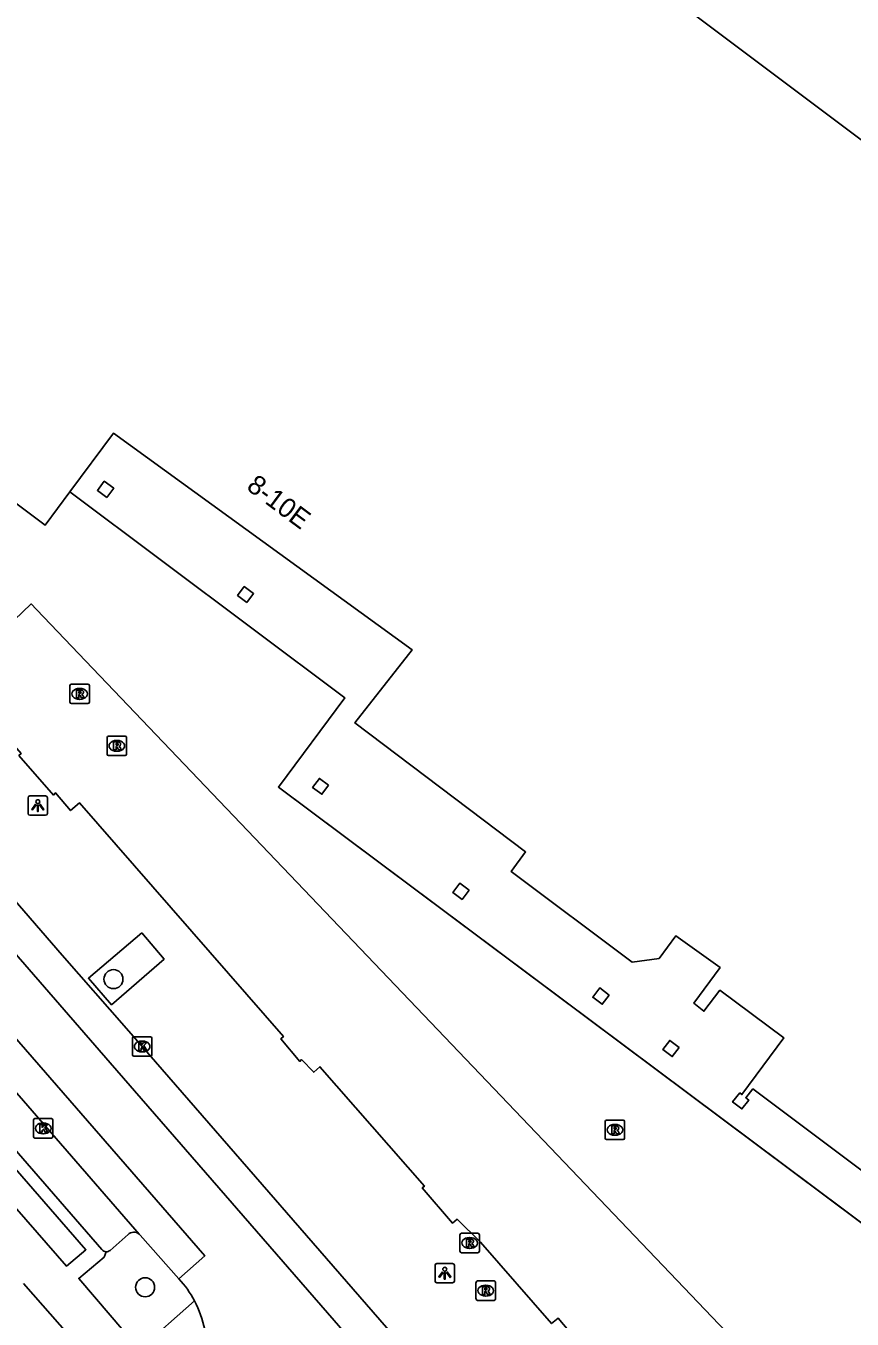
# Model space of a CAD drawing. Extents: x 159718 to 160783, y 383290 to 384030.
# Drawn here: x 160515.5 to 160558, y 383529.7 to 383596.2 of the extents above; entities that cross this region are included whole.
import ezdxf

# ---------------------------------------------------------------- set-up
doc = ezdxf.new("R2010")
doc.units = 0
for name, color, linetype in [('IMGEO_Boom', 7, 'Continuous'), ('IMGEO_Kolk', 7, 'Continuous'), ('IMGEO_Lichtpunt', 7, 'Continuous'), ('IMGEO_Pand', 7, 'Continuous'), ('IMGEO_Pand_nummerreeks', 7, 'Continuous'), ('IMGEO_Pand_overbouw', 7, 'Continuous'), ('IMGEO_Parkeervlak_open', 7, 'Continuous'), ('IMGEO_Rijbaan_lokaal_gesloten', 7, 'Continuous'), ('IMGEO_Rijbaan_lokaal_open', 7, 'Continuous'), ('IMGEO_Rioolput', 7, 'Continuous'), ('IMGEO_Voetpad_open', 7, 'Continuous')]:
    doc.layers.add(name, color=color, linetype=linetype)

msp = doc.modelspace()

# ---------------------------------------------------------------- linework, layer by layer
at = {"layer": 'IMGEO_Boom'}
for centre in [(160520.043, 383547.221), (160521.671, 383531.372)]:
    msp.add_circle(centre, 0.489, dxfattribs=at)
at = {"layer": 'IMGEO_Kolk'}
for p, q in [((160521.019, 383543.333), (160521.019, 383544.185)), ((160521.094, 383544.259), (160521.946, 383544.259)), ((160522.02, 383544.185), (160522.02, 383543.333)), ((160521.53, 383543.479), (160521.505, 383543.479)), ((160521.507, 383544.039), (160521.532, 383544.039)), ((160521.946, 383543.259), (160521.094, 383543.259)), ((160515.929, 383539.121), (160515.929, 383539.973)), ((160516.004, 383540.047), (160516.856, 383540.047)), ((160516.417, 383539.827), (160516.442, 383539.827)), ((160516.93, 383539.973), (160516.93, 383539.121)), ((160516.856, 383539.047), (160516.004, 383539.047)), ((160516.44, 383539.267), (160516.415, 383539.267))]:
    msp.add_line(p, q, dxfattribs=at)
for points in [[(160521.019, 383543.333), (160521.019, 383544.185)], [(160521.094, 383544.259), (160521.946, 383544.259)], [(160522.02, 383544.185), (160522.02, 383543.333)], [(160521.34, 383543.959), (160521.463, 383543.959), (160521.463, 383543.808), (160521.593, 383543.959), (160521.757, 383543.959), (160521.611, 383543.808), (160521.764, 383543.559), (160521.612, 383543.559), (160521.527, 383543.723), (160521.463, 383543.656), (160521.463, 383543.559), (160521.34, 383543.559), (160521.34, 383543.959)], [(160521.946, 383543.259), (160521.094, 383543.259)], [(160515.929, 383539.121), (160515.929, 383539.973)], [(160516.004, 383540.047), (160516.856, 383540.047)], [(160516.25, 383539.747), (160516.373, 383539.747), (160516.373, 383539.596), (160516.503, 383539.747), (160516.667, 383539.747), (160516.521, 383539.596), (160516.674, 383539.347), (160516.522, 383539.347), (160516.437, 383539.511), (160516.373, 383539.444), (160516.373, 383539.347), (160516.25, 383539.347), (160516.25, 383539.747)], [(160516.93, 383539.973), (160516.93, 383539.121)], [(160516.856, 383539.047), (160516.004, 383539.047)]]:
    msp.add_lwpolyline(points, dxfattribs=at)
for centre, start, end in [((160521.096, 383544.183), 91.55205, 178.44795), ((160521.096, 383544.183), 91.55205, 178.44795), ((160521.944, 383544.183), 1.55205, 88.44795), ((160521.944, 383544.183), 1.55205, 88.44795), ((160521.096, 383543.335), 181.55205, 268.44795), ((160521.096, 383543.335), 181.55205, 268.44795), ((160521.944, 383543.335), 271.55205, 358.44795), ((160521.944, 383543.335), 271.55205, 358.44795), ((160516.006, 383539.971), 91.55205, 178.44795), ((160516.006, 383539.971), 91.55205, 178.44795), ((160516.854, 383539.971), 1.55205, 88.44795), ((160516.854, 383539.971), 1.55205, 88.44795), ((160516.006, 383539.123), 181.55205, 268.44795), ((160516.006, 383539.123), 181.55205, 268.44795), ((160516.854, 383539.123), 271.55205, 358.44795), ((160516.854, 383539.123), 271.55205, 358.44795)]:
    msp.add_arc(centre, 0.0765, start, end, dxfattribs=at)
for centre, major_axis, ratio, start_param, end_param in [((160521.506, 383543.759), (-0.387, 0.002), 0.722429, 4.712389, 7.853982), ((160521.531, 383543.759), (-0.39, 0.002), 0.717154, 1.570796, 4.712389), ((160516.416, 383539.547), (-0.387, 0.002), 0.722429, 4.712389, 7.853982), ((160516.441, 383539.547), (-0.39, 0.002), 0.717154, 1.570796, 4.712389)]:
    msp.add_ellipse(centre, major_axis=major_axis, ratio=ratio, start_param=start_param, end_param=end_param, dxfattribs=at)
at = {"layer": 'IMGEO_Lichtpunt'}
for p, q in [((160515.652, 383556.55), (160515.652, 383555.743)), ((160515.652, 383556.55), (160515.652, 383555.743)), ((160516.554, 383556.645), (160515.746, 383556.645)), ((160516.554, 383556.645), (160515.746, 383556.645)), ((160516.648, 383555.743), (160516.648, 383556.55)), ((160516.648, 383555.743), (160516.648, 383556.55)), ((160515.746, 383555.649), (160516.554, 383555.649)), ((160515.746, 383555.649), (160516.554, 383555.649)), ((160536.583, 383532.503), (160536.583, 383531.696)), ((160536.583, 383532.503), (160536.583, 383531.696)), ((160537.485, 383532.598), (160536.677, 383532.598)), ((160537.485, 383532.598), (160536.677, 383532.598)), ((160537.579, 383531.696), (160537.579, 383532.503)), ((160537.579, 383531.696), (160537.579, 383532.503)), ((160536.677, 383531.602), (160537.485, 383531.602)), ((160536.677, 383531.602), (160537.485, 383531.602))]:
    msp.add_line(p, q, dxfattribs=at)
for points in [[(160516.026, 383556.214), (160516.065, 383556.186), (160515.877, 383555.924), (160515.839, 383555.951), (160516.026, 383556.214)], [(160516.128, 383556.166), (160516.175, 383556.166), (160516.175, 383555.844), (160516.128, 383555.844), (160516.128, 383556.166)], [(160516.238, 383556.186), (160516.276, 383556.213), (160516.463, 383555.951), (160516.424, 383555.923), (160516.238, 383556.186)], [(160536.957, 383532.167), (160536.996, 383532.139), (160536.808, 383531.877), (160536.77, 383531.904), (160536.957, 383532.167)], [(160537.169, 383532.139), (160537.207, 383532.166), (160537.394, 383531.904), (160537.355, 383531.876), (160537.169, 383532.139)], [(160537.059, 383532.119), (160537.106, 383532.119), (160537.106, 383531.797), (160537.059, 383531.797), (160537.059, 383532.119)]]:
    msp.add_lwpolyline(points, dxfattribs=at)
for centre in [(160516.151, 383556.348), (160537.082, 383532.301)]:
    msp.add_circle(centre, 0.0994, dxfattribs=at)
for centre, start, end in [((160515.746, 383556.55), 90, 180), ((160515.746, 383556.55), 90, 180), ((160516.554, 383556.55), 0, 90), ((160516.554, 383556.55), 0, 90), ((160515.746, 383555.743), 180, 270), ((160515.746, 383555.743), 180, 270), ((160516.554, 383555.743), 270, 0), ((160516.554, 383555.743), 270, 360), ((160536.677, 383532.503), 90, 180), ((160536.677, 383532.503), 90, 180), ((160537.485, 383532.503), 0, 90), ((160537.485, 383532.503), 0, 90), ((160536.677, 383531.696), 180, 270), ((160536.677, 383531.696), 180, 270), ((160537.485, 383531.696), 270, 0), ((160537.485, 383531.696), 270, 360)]:
    msp.add_arc(centre, 0.0946, start, end, dxfattribs=at)
at = {"layer": 'IMGEO_Pand'}
for points in [[(160493.758, 383632.07), (160498.706, 383632.795), (160500, 383632.985), (160504.256, 383633.608), (160504.664, 383630.755), (160601.88, 383557.855), (160604.224, 383558.191), (160604.335, 383557.571), (160605.212, 383552.648), (160604.956, 383552.602), (160605.685, 383548.516)], [(160517.806, 383572.292), (160516.522, 383570.566), (160510.297, 383575.233), (160510.097, 383576.628), (160510.95, 383577.787), (160505.954, 383581.524), (160506.865, 383582.745)], [(160559.922, 383536.341), (160552.928, 383541.574), (160552.565, 383541.124), (160552.715, 383541.005), (160552.365, 383540.545), (160551.885, 383540.911), (160552.262, 383541.367), (160552.365, 383541.286), (160554.514, 383544.208), (160551.233, 383546.652), (160550.412, 383545.569), (160549.894, 383545.982), (160551.239, 383547.814), (160548.968, 383549.451), (160548.103, 383548.291), (160546.723, 383548.089), (160540.499, 383552.751), (160541.241, 383553.768), (160532.458, 383560.396), (160535.402, 383564.162), (160520.047, 383575.304), (160517.806, 383572.292)], [(160519.703, 383571.99), (160519.214, 383572.354), (160519.571, 383572.833), (160520.059, 383572.469), (160519.703, 383571.99)], [(160526.909, 383566.597), (160526.428, 383566.957), (160526.767, 383567.411), (160527.249, 383567.051), (160526.909, 383566.597)], [(160531.11, 383557.194), (160530.762, 383556.727), (160530.286, 383557.083), (160530.635, 383557.549), (160531.11, 383557.194)], [(160538.337, 383551.806), (160537.973, 383551.318), (160537.499, 383551.672), (160537.863, 383552.16), (160538.337, 383551.806)], [(160545.539, 383546.405), (160545.182, 383545.927), (160544.694, 383546.292), (160545.051, 383546.77), (160545.539, 383546.405)], [(160549.134, 383543.714), (160548.781, 383543.241), (160548.3, 383543.601), (160548.653, 383544.074), (160549.134, 383543.714)], [(160519.644, 383526.744), (160515.423, 383531.566)]]:
    msp.add_lwpolyline(points, dxfattribs=at)
at = {"layer": 'IMGEO_Pand_overbouw'}
msp.add_lwpolyline([(160559.922, 383536.341), (160552.928, 383541.574), (160552.565, 383541.124), (160552.715, 383541.005), (160552.365, 383540.545), (160551.885, 383540.911), (160552.262, 383541.367), (160552.365, 383541.286), (160554.514, 383544.208), (160551.233, 383546.652), (160550.412, 383545.569), (160549.894, 383545.982), (160551.239, 383547.814), (160548.968, 383549.451), (160548.103, 383548.291), (160546.723, 383548.089), (160540.499, 383552.751), (160541.241, 383553.768), (160532.458, 383560.396), (160535.402, 383564.162), (160520.047, 383575.304), (160517.806, 383572.292), (160531.943, 383561.688), (160528.525, 383557.097), (160563.702, 383530.8)], dxfattribs=at)
at = {"layer": 'IMGEO_Parkeervlak_open'}
msp.add_lwpolyline([(160519.865, 383533.273), (160520.796, 383534.085)], dxfattribs=at)
for centre, radius, start, end in [((160521.093, 383533.785), 0.422, 50.60253, 134.66699), ((160519.675, 383533.484), 0.284, 268.02542, 312.07874)]:
    msp.add_arc(centre, radius, start, end, dxfattribs=at)
at = {"layer": 'IMGEO_Rijbaan_lokaal_gesloten'}
for points in [[(160482.526, 383588.525), (160483.151, 383587.858), (160493.318, 383576.241), (160507.09, 383560.37), (160517.403, 383548.451), (160520.715, 383544.684), (160521.52, 383543.759), (160535.801, 383527.329), (160536.623, 383526.415), (160539.338, 383523.165), (160540.32, 383521.963), (160544.286, 383517.022), (160545.265, 383515.781), (160546.841, 383513.764), (160554.904, 383502.868), (160555.82, 383501.543), (160555.982, 383501.307), (160556.128, 383501.1)], [(160477.772, 383584.186), (160479.071, 383585.36), (160490.051, 383572.83), (160501.265, 383559.983), (160524.739, 383532.986), (160523.405, 383531.808)], [(160535.265, 383525.211), (160519.878, 383542.924), (160497.457, 383568.737)], [(160521.361, 383534.111), (160509.108, 383548.222)], [(160523.405, 383531.808), (160521.424, 383534.047), (160521.361, 383534.111)]]:
    msp.add_lwpolyline(points, dxfattribs=at)
at = {"layer": 'IMGEO_Rijbaan_lokaal_open'}
for points in [[(160562.594, 383531.628), (160528.525, 383557.097), (160531.943, 383561.688), (160517.806, 383572.292)], [(160511.866, 383562.752), (160515.816, 383566.523), (160516.087, 383566.239), (160557.707, 383522.642), (160573.646, 383510.923)]]:
    msp.add_lwpolyline(points, dxfattribs=at)
for centre, radius, start, end in [((160519.449, 383528.144), 5.392, 28.01512, 42.80104), ((160519.449, 383528.142), 5.393, 354.69397, 28.04209)]:
    msp.add_arc(centre, radius, start, end, dxfattribs=at)
at = {"layer": 'IMGEO_Rioolput'}
for p, q in [((160517.802, 383561.466), (160517.802, 383562.318)), ((160517.877, 383562.392), (160518.729, 383562.392)), ((160518.29, 383562.172), (160518.315, 383562.172)), ((160518.803, 383562.318), (160518.803, 383561.466)), ((160518.313, 383561.612), (160518.288, 383561.612)), ((160518.729, 383561.392), (160517.877, 383561.392)), ((160519.715, 383558.792), (160519.715, 383559.644)), ((160519.79, 383559.718), (160520.642, 383559.718)), ((160520.203, 383559.498), (160520.228, 383559.498)), ((160520.716, 383559.644), (160520.716, 383558.792)), ((160520.226, 383558.938), (160520.201, 383558.938)), ((160520.642, 383558.718), (160519.79, 383558.718)), ((160545.332, 383539.045), (160545.332, 383539.897)), ((160545.407, 383539.971), (160546.259, 383539.971)), ((160545.82, 383539.751), (160545.845, 383539.751)), ((160546.333, 383539.897), (160546.333, 383539.045)), ((160546.259, 383538.971), (160545.407, 383538.971)), ((160545.843, 383539.191), (160545.818, 383539.191)), ((160537.936, 383534.152), (160538.788, 383534.152)), ((160537.861, 383533.226), (160537.861, 383534.078)), ((160538.349, 383533.932), (160538.374, 383533.932)), ((160538.862, 383534.078), (160538.862, 383533.226)), ((160538.788, 383533.152), (160537.936, 383533.152)), ((160538.372, 383533.372), (160538.347, 383533.372)), ((160538.688, 383530.775), (160538.688, 383531.627)), ((160538.763, 383531.701), (160539.615, 383531.701)), ((160539.176, 383531.481), (160539.201, 383531.481)), ((160539.689, 383531.627), (160539.689, 383530.775)), ((160539.199, 383530.921), (160539.174, 383530.921)), ((160539.615, 383530.701), (160538.763, 383530.701))]:
    msp.add_line(p, q, dxfattribs=at)
for points in [[(160517.802, 383561.466), (160517.802, 383562.318)], [(160517.877, 383562.392), (160518.729, 383562.392)], [(160518.391, 383562.09), (160518.139, 383562.092), (160518.139, 383561.692)], [(160518.803, 383562.318), (160518.803, 383561.466)], [(160518.139, 383561.692), (160518.263, 383561.692), (160518.263, 383561.854), (160518.274, 383561.854)], [(160518.317, 383562.011), (160518.263, 383562.011), (160518.263, 383561.93)], [(160518.263, 383561.93), (160518.315, 383561.93)], [(160518.321, 383561.825), (160518.392, 383561.692), (160518.532, 383561.692), (160518.467, 383561.818)], [(160518.729, 383561.392), (160517.877, 383561.392)], [(160519.715, 383558.792), (160519.715, 383559.644)], [(160519.79, 383559.718), (160520.642, 383559.718)], [(160520.304, 383559.416), (160520.052, 383559.418), (160520.052, 383559.018)], [(160520.716, 383559.644), (160520.716, 383558.792)], [(160520.052, 383559.018), (160520.176, 383559.018), (160520.176, 383559.18), (160520.187, 383559.18)], [(160520.23, 383559.337), (160520.176, 383559.337), (160520.176, 383559.256)], [(160520.176, 383559.256), (160520.228, 383559.256)], [(160520.234, 383559.151), (160520.305, 383559.018), (160520.445, 383559.018), (160520.38, 383559.144)], [(160520.642, 383558.718), (160519.79, 383558.718)], [(160545.332, 383539.045), (160545.332, 383539.897)], [(160545.407, 383539.971), (160546.259, 383539.971)], [(160545.921, 383539.669), (160545.669, 383539.671), (160545.669, 383539.271)], [(160545.847, 383539.59), (160545.793, 383539.59), (160545.793, 383539.509)], [(160545.793, 383539.509), (160545.845, 383539.509)], [(160546.333, 383539.897), (160546.333, 383539.045)], [(160546.259, 383538.971), (160545.407, 383538.971)], [(160545.669, 383539.271), (160545.793, 383539.271), (160545.793, 383539.433), (160545.804, 383539.433)], [(160545.851, 383539.404), (160545.922, 383539.271), (160546.062, 383539.271), (160545.997, 383539.397)], [(160537.936, 383534.152), (160538.788, 383534.152)], [(160537.861, 383533.226), (160537.861, 383534.078)], [(160538.45, 383533.85), (160538.198, 383533.852), (160538.198, 383533.452)], [(160538.198, 383533.452), (160538.322, 383533.452), (160538.322, 383533.614), (160538.333, 383533.614)], [(160538.376, 383533.771), (160538.322, 383533.771), (160538.322, 383533.69)], [(160538.322, 383533.69), (160538.374, 383533.69)], [(160538.38, 383533.585), (160538.451, 383533.452), (160538.591, 383533.452), (160538.526, 383533.578)], [(160538.862, 383534.078), (160538.862, 383533.226)], [(160538.788, 383533.152), (160537.936, 383533.152)], [(160538.688, 383530.775), (160538.688, 383531.627)], [(160538.763, 383531.701), (160539.615, 383531.701)], [(160539.689, 383531.627), (160539.689, 383530.775)], [(160539.277, 383531.399), (160539.025, 383531.401), (160539.025, 383531.001)], [(160539.025, 383531.001), (160539.149, 383531.001), (160539.149, 383531.163), (160539.16, 383531.163)], [(160539.203, 383531.32), (160539.149, 383531.32), (160539.149, 383531.239)], [(160539.149, 383531.239), (160539.201, 383531.239)], [(160539.207, 383531.134), (160539.278, 383531.001), (160539.418, 383531.001), (160539.353, 383531.127)], [(160539.615, 383530.701), (160538.763, 383530.701)]]:
    msp.add_lwpolyline(points, dxfattribs=at)
for centre, radius, start, end in [((160517.879, 383562.316), 0.0765, 91.55205, 178.44795), ((160517.879, 383562.316), 0.0765, 91.55205, 178.44795), ((160518.39, 383561.98), 0.109, 350.36119, 89.41601), ((160518.727, 383562.316), 0.0765, 1.55205, 88.44795), ((160518.727, 383562.316), 0.0765, 1.55205, 88.44795), ((160517.879, 383561.468), 0.0765, 181.55205, 268.44795), ((160517.879, 383561.468), 0.0765, 181.55205, 268.44795), ((160518.273, 383561.801), 0.0533, 26.02933, 88.69889), ((160518.299, 383562.119), 0.19, 274.7715, 282.96867), ((160518.323, 383561.915), 0.0964, 77.00612, 93.18647), ((160518.337, 383561.972), 0.0378, 276.66336, 79.67722), ((160518.388, 383561.98), 0.112, 277.58423, 350.98172), ((160518.372, 383561.765), 0.108, 29.51342, 73.79051), ((160518.727, 383561.468), 0.0765, 271.55205, 358.44795), ((160518.727, 383561.468), 0.0765, 271.55205, 358.44795), ((160519.792, 383559.642), 0.0765, 91.55205, 178.44795), ((160519.792, 383559.642), 0.0765, 91.55205, 178.44795), ((160520.303, 383559.306), 0.109, 350.36119, 89.41601), ((160520.64, 383559.642), 0.0765, 1.55205, 88.44795), ((160520.64, 383559.642), 0.0765, 1.55205, 88.44795), ((160519.792, 383558.794), 0.0765, 181.55205, 268.44795), ((160519.792, 383558.794), 0.0765, 181.55205, 268.44795), ((160520.186, 383559.127), 0.0533, 26.02933, 88.69889), ((160520.212, 383559.445), 0.19, 274.7715, 282.96867), ((160520.236, 383559.241), 0.0964, 77.00612, 93.18647), ((160520.25, 383559.298), 0.0378, 276.66336, 79.67722), ((160520.301, 383559.306), 0.112, 277.58423, 350.98172), ((160520.285, 383559.091), 0.108, 29.51342, 73.79051), ((160520.64, 383558.794), 0.0765, 271.55205, 358.44795), ((160520.64, 383558.794), 0.0765, 271.55205, 358.44795), ((160545.409, 383539.895), 0.0765, 91.55205, 178.44795), ((160545.409, 383539.895), 0.0765, 91.55205, 178.44795), ((160545.829, 383539.698), 0.19, 274.7715, 282.96867), ((160545.853, 383539.494), 0.0964, 77.00612, 93.18647), ((160545.867, 383539.551), 0.0378, 276.66336, 79.67722), ((160545.92, 383539.559), 0.109, 350.36119, 89.41601), ((160545.918, 383539.559), 0.112, 277.58423, 350.98172), ((160546.257, 383539.895), 0.0765, 1.55205, 88.44795), ((160546.257, 383539.895), 0.0765, 1.55205, 88.44795), ((160545.409, 383539.047), 0.0765, 181.55205, 268.44795), ((160545.409, 383539.047), 0.0765, 181.55205, 268.44795), ((160545.803, 383539.38), 0.0533, 26.02933, 88.69889), ((160545.902, 383539.344), 0.108, 29.51342, 73.79051), ((160546.257, 383539.047), 0.0765, 271.55205, 358.44795), ((160546.257, 383539.047), 0.0765, 271.55205, 358.44795), ((160537.938, 383534.076), 0.0765, 91.55205, 178.44795), ((160537.938, 383534.076), 0.0765, 91.55205, 178.44795), ((160538.786, 383534.076), 0.0765, 1.55205, 88.44795), ((160538.786, 383534.076), 0.0765, 1.55205, 88.44795), ((160538.332, 383533.561), 0.0533, 26.02933, 88.69889), ((160538.358, 383533.879), 0.19, 274.7715, 282.96867), ((160538.382, 383533.675), 0.0964, 77.00612, 93.18647), ((160538.396, 383533.732), 0.0378, 276.66336, 79.67722), ((160538.449, 383533.74), 0.109, 350.36119, 89.41601), ((160538.447, 383533.74), 0.112, 277.58423, 350.98172), ((160538.431, 383533.525), 0.108, 29.51342, 73.79051), ((160537.938, 383533.228), 0.0765, 181.55205, 268.44795), ((160537.938, 383533.228), 0.0765, 181.55205, 268.44795), ((160538.786, 383533.228), 0.0765, 271.55205, 358.44795), ((160538.786, 383533.228), 0.0765, 271.55205, 358.44795), ((160538.765, 383531.625), 0.0765, 91.55205, 178.44795), ((160538.765, 383531.625), 0.0765, 91.55205, 178.44795), ((160539.613, 383531.625), 0.0765, 1.55205, 88.44795), ((160539.613, 383531.625), 0.0765, 1.55205, 88.44795), ((160539.159, 383531.11), 0.0533, 26.02933, 88.69889), ((160539.185, 383531.428), 0.19, 274.7715, 282.96867), ((160539.209, 383531.224), 0.0964, 77.00612, 93.18647), ((160539.223, 383531.281), 0.0378, 276.66336, 79.67722), ((160539.276, 383531.289), 0.109, 350.36119, 89.41601), ((160539.274, 383531.289), 0.112, 277.58423, 350.98172), ((160539.258, 383531.074), 0.108, 29.51342, 73.79051), ((160538.765, 383530.777), 0.0765, 181.55205, 268.44795), ((160538.765, 383530.777), 0.0765, 181.55205, 268.44795), ((160539.613, 383530.777), 0.0765, 271.55205, 358.44795), ((160539.613, 383530.777), 0.0765, 271.55205, 358.44795)]:
    msp.add_arc(centre, radius, start, end, dxfattribs=at)
for centre, major_axis, ratio, start_param, end_param in [((160518.289, 383561.892), (-0.387, 0.002), 0.722429, 4.712389, 7.853982), ((160518.314, 383561.892), (-0.39, 0.002), 0.717154, 1.570796, 4.712389), ((160520.202, 383559.218), (-0.387, 0.002), 0.722429, 4.712389, 7.853982), ((160520.227, 383559.218), (-0.39, 0.002), 0.717154, 1.570796, 4.712389), ((160545.819, 383539.471), (-0.387, 0.002), 0.722429, 4.712389, 7.853982), ((160545.844, 383539.471), (-0.39, 0.002), 0.717154, 1.570796, 4.712389), ((160538.348, 383533.652), (-0.387, 0.002), 0.722429, 4.712389, 7.853982), ((160538.373, 383533.652), (-0.39, 0.002), 0.717154, 1.570796, 4.712389), ((160539.175, 383531.201), (-0.387, 0.002), 0.722429, 4.712389, 7.853982), ((160539.2, 383531.201), (-0.39, 0.002), 0.717154, 1.570796, 4.712389)]:
    msp.add_ellipse(centre, major_axis=major_axis, ratio=ratio, start_param=start_param, end_param=end_param, dxfattribs=at)
at = {"layer": 'IMGEO_Voetpad_open'}
for points in [[(160511.866, 383562.752), (160511.89, 383562.724), (160515.293, 383558.818), (160515.179, 383558.723), (160516.954, 383556.691), (160517.061, 383556.806), (160517.833, 383555.891), (160518.301, 383556.281), (160528.78, 383544.263), (160528.653, 383544.157), (160529.631, 383542.99), (160529.714, 383543.088), (160530.342, 383542.429), (160530.657, 383542.715), (160536.038, 383536.571), (160535.924, 383536.485), (160537.472, 383534.677), (160537.713, 383534.871), (160538.911, 383533.701), (160542.576, 383529.504), (160542.912, 383529.792), (160544.85, 383527.489)], [(160521.495, 383549.601), (160522.647, 383548.249), (160519.948, 383545.906), (160518.753, 383547.268), (160521.495, 383549.601)], [(160508.028, 383546.444), (160519.449, 383533.314)], [(160513.49, 383539.175), (160512.494, 383538.315), (160517.634, 383532.459), (160518.623, 383533.307), (160513.49, 383539.175)], [(160519.665, 383533.2), (160519.559, 383532.929), (160518.256, 383531.829), (160521.385, 383528.176)], [(160524.209, 383530.677), (160521.385, 383528.176)]]:
    msp.add_lwpolyline(points, dxfattribs=at)
msp.add_arc((160519.674, 383533.479), 0.279, 216.18999, 268.16182, dxfattribs=at)

# ---------------------------------------------------------------- texts
at = {"layer": 'IMGEO_Pand_nummerreeks'}
msp.add_text('8-10E', height=1, rotation=323.21611, dxfattribs=at).set_placement((160526.83, 383572.444))

doc.saveas('drawing.dxf')
